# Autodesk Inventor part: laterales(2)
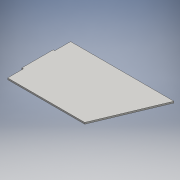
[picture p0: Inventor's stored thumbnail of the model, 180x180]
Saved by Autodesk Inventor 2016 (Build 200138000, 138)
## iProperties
Created: 2016-06
Part Number: laterales(2)
Material: Genérico
Document SubType Name: Modeling
Designer: adm
Density: 1 g/cm^3
Appearance: Valor por defecto
Author: adm
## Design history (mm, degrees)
sketch "Boceto1"
  geometry: L1 (-97, -60)-(50, -60); L2 (100, 60)-(-97, 60); L3 (-100, 30)-(-100, -30); L4 (-100, -60)-(100, 60); L5 (100, -60)-(-100, 60); L6 (100, 60)-(50, -60); L7 (-97, 30)-(-100, 30); L8 (-97, -30)-(-100, -30); L9 (-97, 60)-(-97, 30); L10 (-97, -30)-(-97, -60); 1 further point
  constraints: 20 end point, 2 midpoint, 2 perpendicular, 1 horizontal, 1 parallel
  dimensions: "d0" = 200 distance of L5.end L2.start; "d1" = 120 distance of L2.start L5.start
extrude "Extrusión1" new body sketch "Boceto1" distance "d6" = 3; taper "d7" = 0 deg
node "Sólido1"
other parameters: "d3" = 3
